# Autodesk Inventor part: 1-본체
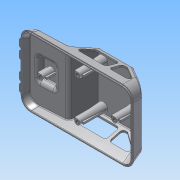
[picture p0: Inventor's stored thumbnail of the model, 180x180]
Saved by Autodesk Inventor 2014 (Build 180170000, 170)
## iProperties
Created: 2015-05
Part Number: 1-본체
Material: ABS 플라스틱
Document SubType Name: Modeling
Designer: Administrator
Density: 1.06 g/cm^3
Appearance: 매끄러움 - 흰색
Mass: 31.9513 g
Surface Area: 305.413 cm^2
Volume: 30.1428 cm^3
Author: Administrator
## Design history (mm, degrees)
sketch "스케치1"
  geometry: L1 (0, 0)-(122, 0); L2 (0, 0)-(2.144, 8); L3 (2.144, 8)-(42, 10.089); L4 (42, 10.089)-(54.442, 30); L5 (54.442, 30)-(92, 30); L6 (92, 30)-(118.738, 12.175); L7 (118.738, 12.175)-(122, 0); L8 (118.738, 12.175)-(122, 10); L9 (122, 10)-(122, 0)
  constraints: 18 end point, 1 collinear, 1 horizontal, 1 parallel, 1 perpendicular
  dimensions: "d0" = 122 distance of L1.start L1.end; "d1" = 8 distance from line of L1 L2.end; "d2" = 105 deg angle of L1 L2; "d3" = 42 horizontal distance of L1.start L3.end; "d4" = 30 horizontal distance of L1.end L5.end; "d6" = 30 horizontal distance of L1.end L5.end; "d7" = 3 deg angle of L1 L3; "d8" = 125 deg angle of L3 L4; "d9" = 20 vertical distance of L8.end L5.end; "d10" = 105 deg angle of L1 L7
extrude "돌출1" new body sketch "스케치1" stored distance "d11" = 76; taper "d12" = 0 deg
sketch "스케치2"
  geometry: L1 (8, 38)-(0, 38) reference; L2 (0, 38)-(0, -38) reference; L3 (0, 38)-(30, 38); L4 (30, 38)-(30, 29.962); L5 (30, 29.962)-(0, 38); L6 (30, -38)-(30, 38) reference; L7 (0, -38)-(30, -29.962); L8 (30, -38)-(0, -38); 1 further point
  constraints: 10 end point, 3 perpendicular, 1 collinear, 1 point on line
  dimensions: "d14" = 105 deg angle of L2 L5; "d51" = 105 deg angle of L2 L7
extrude "돌출2" cut sketch "스케치2" stored distance "d15" = 76; taper "d16" = 0 deg
sketch "스케치9"
  geometry: L1 (8.441, 48.856)-(28.441, 48.856); L2 (28.441, 48.856)-(28.441, 22.856); L3 (28.441, 22.856)-(8.441, 22.856); L4 (8.441, 22.856)-(8.441, 48.856); L5 (-2.559, -2.144)-(-2.559, 73.856) reference; 3 further points
  constraints: 8 end point, 2 midpoint, 2 parallel, 1 horizontal, 1 horizontal alignment, 1 perpendicular
  dimensions: "d59" = 11 distance between parallel lines of L4 L5; "d60" = 20 distance of L1.start L1.end; "d61" = 26 distance of L3.end L1.start
extrude "돌출7" join sketch "스케치9" distance "d62" = 5; taper "d63" = -20 deg
fillet "모깎기1" dims "d18" = 12, "d19" = 3
fillet "모깎기2" dims "d20" = 3
feature "쉘1" dims "d17" = 2
sketch "스케치3"
  geometry: L1 (91.092, 30)-(56.105, 30) reference; L2 (53.561, 28.59)-(42.828, 11.413) reference; L3 (81.84, 25)-(57.213, 25); L4 (57.213, 25)-(47.84, 10); L5 (47.84, 10)-(81.84, 10); L6 (81.84, 10)-(81.84, 25); L7 (84.986, 25)-(84.986, 10); L8 (84.986, 10)-(112.986, 10); L9 (107.213, 19.858)-(92.756, 29.496) reference; L10 (112.986, 10)-(90.486, 25); L11 (84.986, 25)-(90.486, 25); 1 further point
  constraints: 16 end point, 6 parallel, 2 perpendicular, 1 collinear, 1 point on line
  dimensions: "d21" = 5 distance between parallel lines of L4 L2; "d22" = 5 distance between parallel lines of L3 L1; "d23" = 15 distance between parallel lines of L5 L3; "d24" = 34 distance of L4.end L5.end; "d25" = 5 distance between parallel lines of L9 L10; "d26" = 28 distance of L7.end L8.end
extrude "돌출3" cut sketch "스케치3" stored distance "d27" = 0; taper "d28" = 0 deg
fillet "모깎기3" dims "d29" = 3
sketch "스케치5"
  geometry: L1 (0.139, -2.071)-(98.679, -2.071) reference; L2 (108.338, -11.73)-(108.338, -64.27) reference; L3 (-9.521, -64.27)-(-9.521, -11.73) reference; L4 (98.679, -73.929)-(0.139, -73.929) reference; L5 (-10.521, -11.73)-(-10.521, -64.27); L6 (0.139, -74.929)-(98.679, -74.929); L7 (109.338, -64.27)-(109.338, -11.73); L8 (98.679, -1.071)-(0.139, -1.071); 8 further points; 5 other entities
  constraints: 8 end point, 7 parallel, 17 other
  dimensions: "d52" = 1 distance between parallel lines of L3 L5
extrude "돌출4" join sketch "스케치5" distance "d32" = 1; taper "d33" = 0 deg
node "작업 평면1"
sketch "스케치6"
  geometry: L1 (0, 25)-(0, 17); L2 (0, 14)-(0, 6); L3 (0, -6)-(0, -14); L4 (0, -17)-(0, -25); A1 r 4 centre (0, 21) between (0, 25) and (0, 17); A2 r 4 centre (0, 10) between (0, 14) and (0, 6); A3 r 4 centre (0, -10) between (0, -6) and (0, -14); A4 r 4 centre (0, -21) between (0, -17) and (0, -25); 4 further points
  constraints: 8 end point, 8 point on circle, 4 centre point, 13 other
  dimensions: "d35" = 8 diameter of A1; "d36" = 8 diameter of A2; "d37" = 8 diameter of A3; "d38" = 8 diameter of A4; "d39" = 20 distance of A3.centre A2.centre; "d40" = 11 distance of A2.centre A1.centre; "d41" = 11 distance of A4.centre A3.centre; "d42" = 10 distance of point (0, 0) A3.centre
extrude "돌출5" join sketch "스케치6" stored distance "d43" = 1; taper "d44" = 0 deg
chamfer "모따기1" distance "d45" = 1; stored, may be unused: second distance "d46" = 2, angle "d47" = 45 deg
sketch "스케치7"
  geometry: L1 (65.895, 54.068)-(65.895, 1.251) reference; 3 further points
  constraints: 1 horizontal alignment, 1 midpoint, 1 other
  dimensions: "d53" = 50 distance from line of L1 point (15.895, 27.66)
feature "엠보싱1" sketch "스케치7" dims "d49" = 0.5, "d50" = 0
sketch "스케치10"
  geometry: L1 (-11.591, 44)-(-11.591, 32) reference; L2 (110.409, 11.591)-(110.409, 64.409) reference; C1 r 3 at (9.409, 38); C2 r 3 at (89.409, 38); C3 r 3 at (49.409, 16); C4 r 3 at (49.409, 60); 2 further points
  constraints: 4 centre point, 3 equal radius, 2 horizontal alignment, 1 midpoint, 1 vertical alignment
  dimensions: "d64" = 6 diameter of C1; "d65" = 21 distance from line of C2.centre L2; "d66" = 40 horizontal distance of C3.centre C2.centre; "d67" = 22 vertical distance of point (-11.591, 38) C3.centre; "d68" = 44 distance of C3.centre C4.centre; "d69" = 40 horizontal distance of C3.centre C1.centre
extrude "돌출8" join sketch "스케치10" stored distance "d70" = 5; taper "d71" = 4 deg
node "작업 평면2"
sketch "스케치11"
  geometry: L1 (-45, 21)-(-35, 21); L2 (-35, 21)-(-35, 23); L3 (-35, 23)-(-45, 23); L4 (-45, 23)-(-45, 21); L5 (-45, 21)-(-35, 23); L6 (-35, 21)-(-45, 23); L7 (-85, -1)-(-75, -1); L8 (-75, -1)-(-75, 1); L9 (-75, 1)-(-85, 1); L10 (-85, -1)-(-75, 1); L11 (-75, -1)-(-85, 1); L12 (-45, -23)-(-35, -23); L13 (-35, -23)-(-35, -21); L14 (-35, -21)-(-45, -21); L15 (-45, -21)-(-45, -23); L16 (-45, -23)-(-35, -21); L17 (-35, -23)-(-45, -21); L18 (-5, -1)-(5, -1); L19 (5, -1)-(5, 1); L20 (5, 1)-(-5, 1); L21 (-5, 1)-(-5, -1); L22 (-5, -1)-(5, 1); L23 (5, -1)-(-5, 1); L24 (-85, 1)-(-85, -1); C1 r 3 at (-40, 22) reference; C2 r 3 at (-80, 0) reference; C3 r 3 at (-40, -22) reference; C4 r 3 at (0, 0) reference; 1 further point
  constraints: 48 end point, 8 midpoint, 8 parallel, 6 equal length, 4 horizontal, 4 perpendicular
  dimensions: "d73" = 10 distance of L1.start L1.end; "d74" = 2 distance of L1.end L2.end
extrude "돌출11" join sketch "스케치11" stored distance "d93" = 0; taper "d94" = 0 deg
sketch "스케치15"
  geometry: C1 r 3 at (0, 0) reference; C2 r 3 at (-40, -22) reference; C3 r 3 at (0, -44) reference; C4 r 3 at (40, -22) reference; 5 further points
  constraints: 4 coincident
hole "구멍1" sketch "스케치15" at (0, 0), (-40, -22), (0, -44), (40, -22) diameter "d95" = 3.242; stored, may be unused: countersink angle "d99" = 90 deg, drill point angle "d101" = 118 deg; dims "d96" = 9, "d97" = 4, "d98" = 2, "d100" = 11
node "솔리드1"
node "투영된 루프1"
node "투영된 루프2"
node "투영된 루프3"
node "투영된 루프4"
node "투영된 루프5"
node "투영된 루프6"
other parameters: "d34" = -2, "d72" = -2
